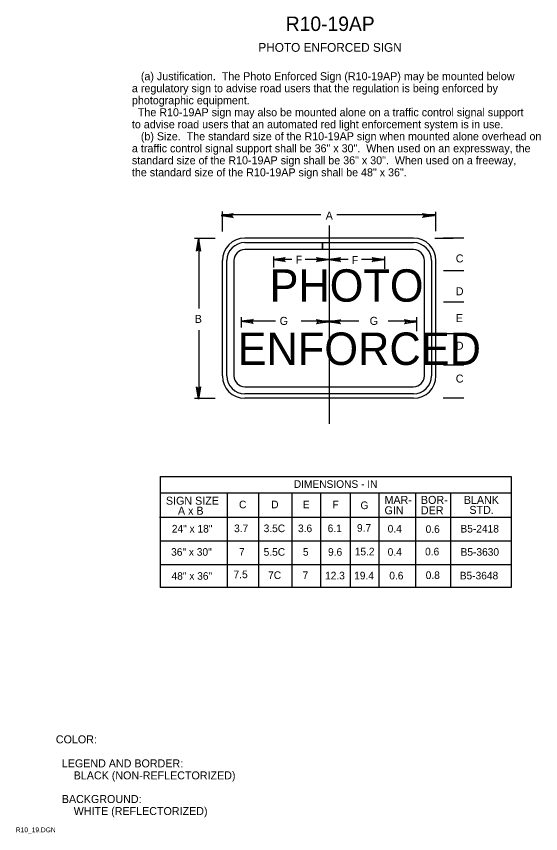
# Model space of a CAD drawing. Extents: x 0.013 to 0.177, y 0.004 to 0.259.
import ezdxf

# ---------------------------------------------------------------- set-up
doc = ezdxf.new("R2010")
doc.units = 0
for name, color, linetype in [('1', 7, 'Continuous'), ('2', 7, 'Continuous'), ('3', 7, 'Continuous')]:
    doc.layers.add(name, color=color, linetype=linetype)

# ---------------------------------------------------------------- blocks, each defined once
blk = doc.blocks.new('RARROW')
at = {"layer": '3'}
for p, q in [((-2.156, 0.285), (-2.2665, 0.384625)), ((-2.2665, 0.384625), (0, 0)), ((0, 0), (-2.2665, -0.379125)), ((-2.156, 0.285), (-2.075625, 0.12075)), ((0, 0), (-2.156, 0.285)), ((-2.14975, -0.2705), (0, 0)), ((-2.075625, 0.12075), (0, 0)), ((0, 0), (-2.074, -0.108)), ((-2.2665, -0.379125), (-2.14975, -0.2705)), ((-2.074, -0.108), (-2.14975, -0.2705))]:
    blk.add_line(p, q, dxfattribs=at)

msp = doc.modelspace()

# ---------------------------------------------------------------- linework, layer by layer
at = {"layer": '1'}
for p, q in [((0.11046, 0.1938), (0.11046, 0.13182)), ((0.06841, 0.18983), (0.07491, 0.18983)), ((0.06987, 0.16791), (0.06987, 0.18983)), ((0.13681, 0.18984), (0.08411, 0.18984)), ((0.15252, 0.18983), (0.14602, 0.18983)), ((0.08411, 0.18844), (0.10838, 0.18844)), ((0.10838, 0.18624), (0.08411, 0.18624)), ((0.10838, 0.18844), (0.10838, 0.18624)), ((0.10838, 0.18844), (0.10838, 0.18624)), ((0.10838, 0.18624), (0.10838, 0.18844)), ((0.10838, 0.18844), (0.13681, 0.18844)), ((0.13681, 0.18624), (0.10838, 0.18624)), ((0.09311, 0.18414), (0.09311, 0.18072)), ((0.12776, 0.18414), (0.12776, 0.18026)), ((0.07711, 0.14684), (0.07711, 0.18284)), ((0.07851, 0.14684), (0.07851, 0.18284)), ((0.08071, 0.18284), (0.08071, 0.14684)), ((0.14021, 0.14684), (0.14021, 0.18284)), ((0.14241, 0.18284), (0.14241, 0.14684)), ((0.14381, 0.14684), (0.14381, 0.18284)), ((0.14381, 0.14684), (0.14381, 0.18284)), ((0.15252, 0.17965), (0.14613, 0.17965)), ((0.15252, 0.16987), (0.14613, 0.16987)), ((0.08313, 0.16194), (0.08313, 0.16516)), ((0.13779, 0.16079), (0.13779, 0.16516)), ((0.06987, 0.13984), (0.06987, 0.16114)), ((0.14613, 0.16009), (0.15252, 0.16009)), ((0.14613, 0.15031), (0.15252, 0.15031)), ((0.08411, 0.14344), (0.13681, 0.14344)), ((0.13681, 0.14124), (0.08411, 0.14124)), ((0.06841, 0.13984), (0.07491, 0.13984)), ((0.13681, 0.13984), (0.08411, 0.13984)), ((0.15252, 0.13984), (0.14602, 0.13984))]:
    msp.add_line(p, q, dxfattribs=at)
for centre, radius, start, end in [((0.08411, 0.18284), 0.007, 90, 180), ((0.13681, 0.18284), 0.007, 0, 90), ((0.08411, 0.18284), 0.0056, 90, 180), ((0.08411, 0.18284), 0.0034, 90, 180), ((0.13681, 0.18284), 0.0056, 0, 90), ((0.13681, 0.18284), 0.0034, 0, 90), ((0.08411, 0.14684), 0.007, 180, 270), ((0.08411, 0.14684), 0.0056, 180, 270), ((0.08411, 0.14684), 0.0034, 180, 270), ((0.13681, 0.14684), 0.007, 270, 0), ((0.13681, 0.14684), 0.0034, 270, 0), ((0.13681, 0.14684), 0.0056, 270, 0)]:
    msp.add_arc(centre, radius, start, end, dxfattribs=at)
at = {"layer": '3'}
for p, q in [((0.07711, 0.19187), (0.07711, 0.19815)), ((0.10784, 0.19714), (0.07711, 0.19714)), ((0.1438, 0.19714), (0.11291, 0.19714)), ((0.14381, 0.19197), (0.1438, 0.198)), ((0.14346, 0.18985), (0.14923, 0.18985)), ((0.09877, 0.18321), (0.09311, 0.18321)), ((0.11046, 0.18321), (0.10293, 0.18321)), ((0.11644, 0.18321), (0.11046, 0.18321)), ((0.12776, 0.18321), (0.1206, 0.18321)), ((0.09374, 0.1639), (0.08313, 0.16391)), ((0.11046, 0.16388), (0.10174, 0.16389)), ((0.1197, 0.16387), (0.11046, 0.16388)), ((0.13779, 0.16387), (0.12891, 0.16388)), ((0.05774, 0.11538), (0.16725, 0.11538)), ((0.05774, 0.11538), (0.05774, 0.08079)), ((0.16726, 0.11544), (0.16726, 0.08079)), ((0.16726, 0.11025), (0.05774, 0.11025)), ((0.07858, 0.11025), (0.07858, 0.08079)), ((0.1374, 0.11025), (0.1374, 0.08079)), ((0.14834, 0.11025), (0.14834, 0.08079)), ((0.0575, 0.10275), (0.16725, 0.10275)), ((0.05775, 0.09538), (0.16725, 0.09538)), ((0.05775, 0.088), (0.16725, 0.088)), ((0.16726, 0.08079), (0.05774, 0.08079))]:
    msp.add_line(p, q, dxfattribs=at)
for points in [[(0.08839, 0.11025), (0.08839, 0.08079)], [(0.09882, 0.11025), (0.09882, 0.08079)], [(0.10774, 0.11025), (0.10774, 0.08079)], [(0.11699, 0.11025), (0.11699, 0.08079)], [(0.12602, 0.11025), (0.12602, 0.08079)]]:
    msp.add_lwpolyline(points, dxfattribs=at)

# ---------------------------------------------------------------- block references
for p, xscale, yscale, rotation in [((0.07675, 0.19687), 0.0016545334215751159, 0.0016366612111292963, 179.91708286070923), ((0.14338, 0.19687), 0.0016545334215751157, 0.001636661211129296, -0.08291713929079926), ((0.06963, 0.1895), 0.0016545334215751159, 0.0016366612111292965, 90.08291713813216), ((0.093, 0.18313), 0.0016545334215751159, 0.0016366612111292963, 179.91708286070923), ((0.11025, 0.18313), 0.0016545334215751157, 0.001636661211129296, -0.08291713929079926), ((0.11025, 0.18313), 0.0016545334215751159, 0.0016366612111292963, 179.91708286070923), ((0.12763, 0.18313), 0.0016545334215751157, 0.001636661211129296, -0.08291713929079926), ((0.083, 0.16387), 0.0016545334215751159, 0.0016366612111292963, 179.91708286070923), ((0.11025, 0.16375), 0.0016545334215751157, 0.001636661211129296, -0.08291713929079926), ((0.11025, 0.16375), 0.0016545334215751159, 0.0016366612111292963, 179.91708286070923), ((0.13775, 0.16375), 0.0016545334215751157, 0.001636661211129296, -0.08291713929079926), ((0.06963, 0.13962), 0.0016545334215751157, 0.0016366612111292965, -89.91708286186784)]:
    msp.add_blockref('RARROW', p, dxfattribs=dict(at, xscale=xscale, yscale=yscale, rotation=rotation))

# ---------------------------------------------------------------- texts
at = {"layer": '1'}
for s, height, p in [('R10-19AP', 0.0045, (0.09691, 0.2545)), ('PHOTO ENFORCED SIGN', 0.0027503, (0.08837, 0.248)), ('PHOTO', 0.010107, (0.09187, 0.17)), ('ENFORCED', 0.010125, (0.08188, 0.15025)), ('7', 0.00238, (0.08231, 0.09069)), ('5.5C', 0.002375, (0.09001, 0.09069)), ('5', 0.00238, (0.10227, 0.09069)), ('9.6', 0.002375, (0.11012, 0.09069)), ('15.2', 0.002375, (0.11845, 0.09081)), ('0.4', 0.002375, (0.12873, 0.09069)), ('0.8', 0.002375, (0.14061, 0.08344)), ('B5-3648', 0.002375, (0.15124, 0.08331)), ('COLOR:', 0.0025, (0.02513, 0.03213)), ('  LEGEND AND BORDER:', 0.0024998, (0.02513, 0.02463)), ('      BLACK (NON-REFLECTORIZED)', 0.0024998, (0.02513, 0.02088)), ('  BACKGROUND:', 0.0024998, (0.02513, 0.0135)), ('      WHITE (REFLECTORIZED)', 0.0024998, (0.02513, 0.00975)), ('R10_19.DGN', 0.0015, (0.01263, 0.00438))]:
    msp.add_text(s, height=height, dxfattribs=at).set_placement(p)
at = {"layer": '2'}
for s, p in [('   (a) Justification.  The Photo Enforced Sign (R10-19AP) may be mounted below', (0.04888, 0.23913)), ('a regulatory sign to advise road users that the regulation is being enforced by', (0.04888, 0.23538)), ('photographic equipment.', (0.04888, 0.23163)), ('  The R10-19AP sign may also be mounted alone on a traffic control signal support', (0.04888, 0.22788)), ('to advise road users that an automated red light enforcement system is in use.', (0.04888, 0.22413)), ('   (b) Size.  The standard size of the R10-19AP sign when mounted alone overhead on', (0.04888, 0.22038)), ('a traffic control signal support shall be 36" x 30".  When used on an expressway, the', (0.04888, 0.21663)), ('standard size of the R10-19AP sign shall be 36" x 30".  When used on a freeway, ', (0.04888, 0.21288)), ('the standard size of the R10-19AP sign shall be 48" x 36".', (0.04888, 0.20913))]:
    msp.add_text(s, height=0.0024998, dxfattribs=at).set_placement(p)
at = {"layer": '3'}
for s, rotation, p in [('A', 359.9171, (0.10938, 0.19562)), ('F', 359.9171, (0.1, 0.18188)), ('F', 0.0829, (0.1175, 0.18175)), ('C', 0.0829, (0.15, 0.18225)), ('D', 359.9171, (0.15, 0.172)), ('B', 0.0829, (0.0685, 0.16337)), ('E', 0.0829, (0.15, 0.16362)), ('G', 359.9171, (0.095, 0.16275)), ('G', 0.0829, (0.12312, 0.16275)), ('D', 0.0829, (0.15, 0.155)), ('C', 359.9171, (0.15, 0.14475))]:
    msp.add_text(s, height=0.0025, rotation=rotation, dxfattribs=at).set_placement(p)
for s, height, p in [('DIMENSIONS - IN', 0.0023752, (0.09942, 0.11188)), ('SIGN SIZE', 0.0025, (0.0595, 0.10662)), ('C', 0.00238, (0.08232, 0.1055)), ('D', 0.00238, (0.09236, 0.1055)), ('E', 0.00238, (0.10221, 0.1055)), ('F', 0.00238, (0.11149, 0.1055)), ('G', 0.00238, (0.12025, 0.10525)), ('MAR-', 0.0025, (0.12775, 0.10687)), ('BOR-', 0.0025, (0.13912, 0.10687)), ('BLANK', 0.0025, (0.1525, 0.10687)), ('A x B', 0.0025, (0.06325, 0.1035)), ('GIN', 0.0025, (0.12775, 0.10363)), ('DER', 0.0025, (0.13912, 0.10363)), ('STD.', 0.0025, (0.15425, 0.10375)), ('24" x 18"', 0.002375, (0.06134, 0.09794)), ('3.7', 0.002375, (0.08078, 0.09806)), ('3.5C', 0.002375, (0.09001, 0.09806)), ('3.6', 0.002375, (0.10074, 0.09806)), ('6.1', 0.002375, (0.10999, 0.09806)), ('9.7', 0.002375, (0.11915, 0.09819)), ('0.4', 0.002375, (0.12873, 0.09794)), ('0.6', 0.002375, (0.14058, 0.09781)), ('B5-2418', 0.002375, (0.15146, 0.09794)), ('36" x 30"', 0.002375, (0.06112, 0.09069)), ('0.6', 0.002375, (0.14042, 0.09081)), ('B5-3630', 0.002375, (0.1515, 0.09069)), ('48" x 36"', 0.002375, (0.06125, 0.08319)), ('7.5', 0.002375, (0.08062, 0.08369)), ('7C', 0.002375, (0.09141, 0.08344)), ('7', 0.00238, (0.10218, 0.08344)), ('12.3', 0.002375, (0.10918, 0.08331)), ('19.4', 0.002375, (0.11826, 0.08331)), ('0.6', 0.002375, (0.12924, 0.08331))]:
    msp.add_text(s, height=height, dxfattribs=at).set_placement(p)

doc.saveas('drawing.dxf')
